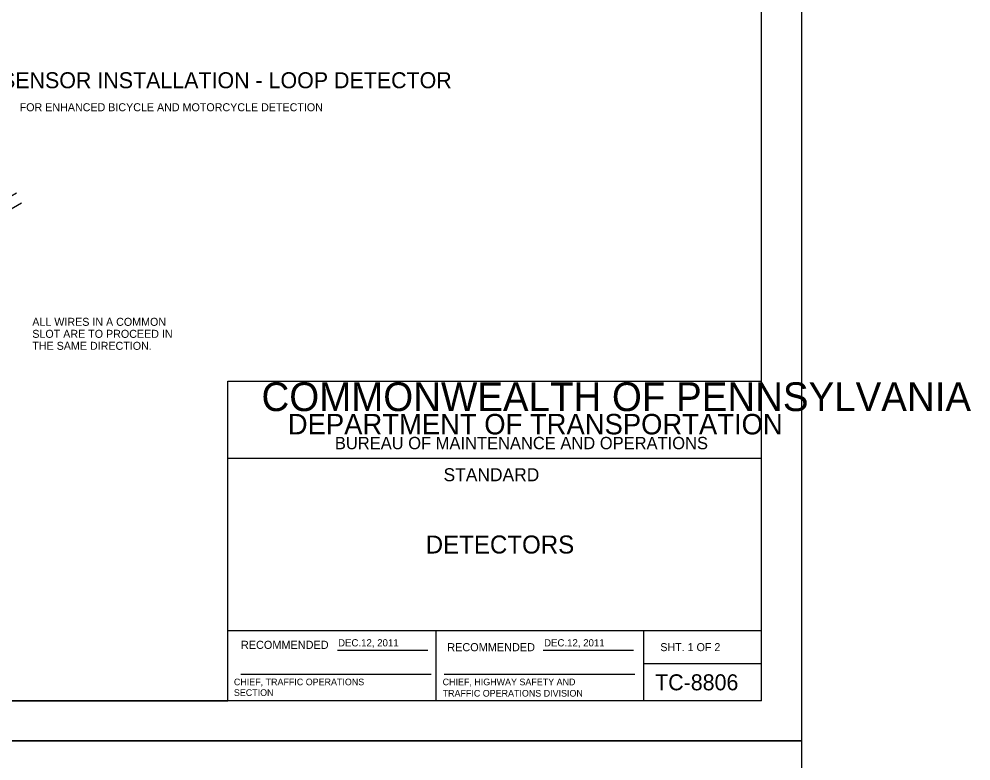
# Model space of a CAD drawing. Extents: x 2709 to 3899, y 22 to 1210.
# Drawn here: x 3256.6 to 3613.4, y 608.7 to 886.9 of the extents above; entities that cross this region are included whole.
import ezdxf

# ---------------------------------------------------------------- set-up
doc = ezdxf.new("R2010")
doc.units = 0
for name, color, linetype in [('1', 7, 'Continuous'), ('17', 7, 'Continuous'), ('2', 7, 'Continuous'), ('4', 7, 'Continuous'), ('Default', 7, 'Continuous'), ('PLT-BNDY', 7, 'Continuous')]:
    doc.layers.add(name, color=color, linetype=linetype)

msp = doc.modelspace()

# ---------------------------------------------------------------- linework, layer by layer
at = {"layer": '1'}
for p, q in [((3534.86, 631.17), (3534.86, 1195.17)), ((3334.86, 631.17), (3334.86, 751.17)), ((3334.86, 751.17), (3534.86, 751.17)), ((3534.86, 722.17), (3334.86, 722.17)), ((3334.86, 657.55), (3534.86, 657.55)), ((3412.86, 657.55), (3412.86, 631.17)), ((3490.73, 631.17), (3490.73, 657.55)), ((3375.9, 650.2), (3409.82, 650.2)), ((3452.99, 650.2), (3486.91, 650.2)), ((3490.73, 645.17), (3534.86, 645.17)), ((3339.74, 641.21), (3411.07, 641.21)), ((3415.95, 641.21), (3487.41, 641.21)), ((3534.86, 631.17), (2748.86, 631.17)), ((2748.86, 631.17), (3334.86, 631.17))]:
    msp.add_line(p, q, dxfattribs=at)
at = {"layer": '2'}
msp.add_lwpolyline([(3255.55, 821.67), (3244.8, 815.42), (3235.05, 825.17), (3223.42, 813.67), (3223.42, 721.17), (3208.67, 706.42), (3194.8, 720.17), (3194.8, 812.67), (3206.42, 824.3), (3217.92, 812.67), (3217.92, 720.17), (3232.67, 705.42), (3246.55, 719.3), (3246.55, 811.8), (3257.42, 818.05)], dxfattribs=at)
at = {"layer": 'PLT-BNDY'}
for points in [[(2708.86, 1210.17), (3549.86, 1210.17), (3549.86, 616.17), (2708.86, 616.17)], [(2708.86, 616.17), (3549.86, 616.17), (3549.86, 22.17), (2708.86, 22.17)]]:
    msp.add_lwpolyline(points, close=True, dxfattribs=at)

# ---------------------------------------------------------------- texts
at = {"layer": '1'}
for s, height, p in [('COMMONWEALTH OF PENNSYLVANIA', 10.7828, (3347.45, 739.9)), ('DEPARTMENT OF TRANSPORTATION', 7.6837, (3357.31, 731.15)), ('BUREAU OF MAINTENANCE AND OPERATIONS', 4.6253, (3374.95, 725.59)), ('DETECTORS', 6.75, (3409.01, 686.48)), ('RECOMMENDED', 3.0516, (3339.73, 650.7)), ('RECOMMENDED', 3.0516, (3417.08, 649.82)), ('SHT. 1 OF 2', 3, (3496.94, 649.86)), ('TC-8806', 6, (3495, 635.17))]:
    msp.add_text(s, height=height, dxfattribs=at).set_placement(p)
at = {"layer": '17'}
msp.add_text('FOR ENHANCED BICYCLE AND MOTORCYCLE DETECTION', height=3, dxfattribs=at).set_placement((3256.79, 852.35))
at = {"layer": '2'}
for s, height, p in [('ALTERNATE SENSOR INSTALLATION - LOOP DETECTOR', 6, (3200.31, 860.98)), ('ALL WIRES IN A COMMON', 3, (3261.52, 771.87)), ('SLOT ARE TO PROCEED IN', 3, (3261.52, 767.37)), ('THE SAME DIRECTION.', 3, (3261.52, 762.87)), ('DEC.12, 2011', 2.7032, (3376.15, 651.64))]:
    msp.add_text(s, height=height, dxfattribs=at).set_placement(p)
msp.add_text('DEC.12, 2011', height=2.7032, rotation=360, dxfattribs=at).set_placement((3453.37, 651.64))
at = {"layer": '4'}
msp.add_text('STANDARD', height=4.881, rotation=360, dxfattribs=at).set_placement((3415.69, 713.59))
at = {"layer": 'Default'}
for s, p in [('CHIEF, TRAFFIC OPERATIONS', (3337.1, 637.06)), ('CHIEF, HIGHWAY SAFETY AND', (3415.35, 637.06)), ('SECTION', (3337.1, 633.06)), ('TRAFFIC OPERATIONS DIVISION', (3415.35, 632.81))]:
    msp.add_text(s, height=2.5, dxfattribs=at).set_placement(p)

doc.saveas('drawing.dxf')
